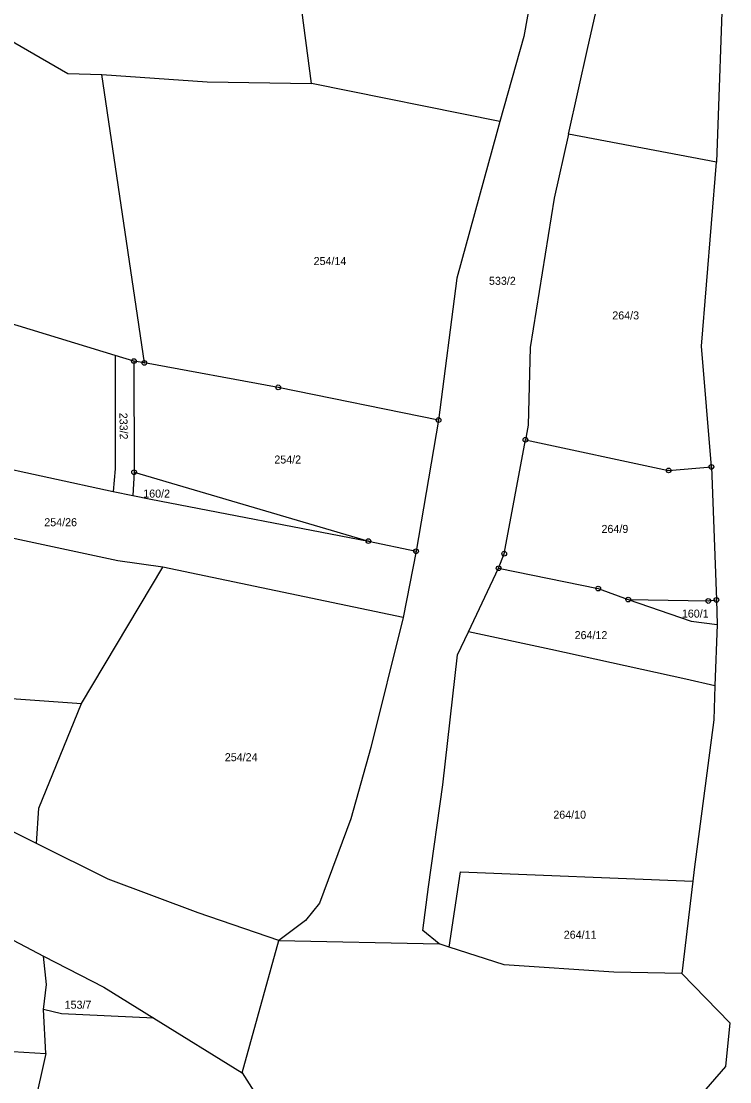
# Model space of a CAD drawing. Extents: x -725728 to -720881, y -1068679 to -1063504.
# Drawn here: x -725062.3 to -724911.7, y -1067027.7 to -1066802.4 of the extents above; entities that cross this region are included whole.
import ezdxf

# ---------------------------------------------------------------- set-up
doc = ezdxf.new("R2010")
doc.units = 0
for name, color, linetype in [('Hranice parcel', 7, 'Continuous'), ('Parcelní čísla', 7, 'Continuous'), ('Značky bodu BP', 7, 'Continuous')]:
    doc.layers.add(name, color=color, linetype=linetype)

# ---------------------------------------------------------------- blocks, each defined once
blk = doc.blocks.new('1.05_1')
at = {"layer": 'Značky bodu BP'}
for radius in [0.05, 0.00303]:
    blk.add_circle((0, 0), radius, dxfattribs=at)
blk = doc.blocks.new('1.05_2')
at = {"layer": 'Značky bodu BP'}
for radius in [0.05, 0.00303]:
    blk.add_circle((0, 0), radius, dxfattribs=at)

msp = doc.modelspace()

# ---------------------------------------------------------------- linework, layer by layer
at = {"layer": 'Hranice parcel'}
for p, q in [((-725000.59, -1066815.68), (-725010.55, -1066741.09)), ((-725036.09, -1066875.04), (-725045.16, -1066813.74)), ((-724960.58, -1066823.72), (-725000.59, -1066815.68)), ((-724914.54, -1066832.38), (-724945.99, -1066826.46)), ((-725038.32, -1066874.63), (-725042.27, -1066873.43)), ((-725038.32, -1066874.63), (-725038.29, -1066898.25)), ((-725036.09, -1066875.04), (-725038.32, -1066874.63)), ((-724973.6, -1066887.19), (-724978.39, -1066915.04)), ((-724959.66, -1066915.55), (-724955.14, -1066891.36)), ((-724915.65, -1066897.11), (-724914.58, -1066925.38)), ((-725038.29, -1066898.25), (-725038.58, -1066903.16)), ((-725038.29, -1066898.25), (-724988.52, -1066912.87)), ((-725042.75, -1066902.35), (-725038.58, -1066903.16)), ((-724988.52, -1066912.87), (-724978.39, -1066915.04)), ((-724978.39, -1066915.04), (-724981.09, -1066929.13)), ((-724960.85, -1066918.65), (-724959.66, -1066915.55)), ((-725049.48, -1066947.41), (-725032.2, -1066918.45)), ((-724981.09, -1066929.13), (-725032.2, -1066918.45)), ((-724967.25, -1066932.12), (-724960.85, -1066918.65)), ((-724960.85, -1066918.65), (-724939.69, -1066922.96)), ((-724939.69, -1066922.96), (-724933.32, -1066925.29)), ((-724914.58, -1066925.38), (-724914.39, -1066930.62)), ((-724914.39, -1066930.62), (-724914.89, -1066943.64)), ((-725117.44, -1066942.46), (-725049.48, -1066947.41)), ((-724919.62, -1066985.13), (-724921.91, -1067004.75)), ((-725015.32, -1067025.8), (-725007.51, -1066997.75)), ((-725007.51, -1066997.75), (-724973.45, -1066998.45)), ((-724971.34, -1066999.13), (-724973.45, -1066998.45)), ((-725057, -1067021.75), (-725057.49, -1067012.35)), ((-725034.06, -1067014.24), (-725015.32, -1067025.8)), ((-725057, -1067021.75), (-725074.77, -1067099.53))]:
    msp.add_line(p, q, dxfattribs=at)
for points in [[(-724943.71, -1066712.36), (-724942.26, -1066725.91), (-724945.82, -1066756.96), (-724951.11, -1066781.29), (-724955.47, -1066805.69), (-724960.58, -1066823.72)], [(-724945.99, -1066826.46), (-724941.87, -1066808.05), (-724933.67, -1066771.83), (-724930.31, -1066746.2), (-724928.58, -1066730.81)], [(-724912.15, -1066776.37), (-724913.1, -1066790.55), (-724914.54, -1066832.38)], [(-725100.64, -1066785.59), (-725052.38, -1066813.57), (-725045.16, -1066813.74)], [(-725045.16, -1066813.74), (-725022.74, -1066815.34), (-725000.59, -1066815.68)], [(-724960.58, -1066823.72), (-724961.26, -1066826.11), (-724969.71, -1066857.04), (-724973.6, -1066887.19)], [(-724945.99, -1066826.46), (-724949.03, -1066840.06), (-724954.11, -1066871.75), (-724954.56, -1066888.28), (-724955.14, -1066891.36)], [(-724915.65, -1066897.11), (-724917.76, -1066871.46), (-724914.54, -1066832.38)], [(-725042.27, -1066873.43), (-725099.08, -1066856.11), (-725117.05, -1066852.4)], [(-725042.27, -1066873.43), (-725042.27, -1066897.54), (-725042.75, -1066902.35)], [(-724973.6, -1066887.19), (-725007.66, -1066880.22), (-725036.09, -1066875.04)], [(-725125.27, -1066884.94), (-725097.48, -1066890.47), (-725042.75, -1066902.35)], [(-724955.14, -1066891.36), (-724924.73, -1066897.86), (-724915.65, -1066897.11)], [(-725032.2, -1066918.45), (-725041.72, -1066917.05), (-725097.95, -1066905.02), (-725128.28, -1066896.83)], [(-725038.58, -1066903.16), (-725034.75, -1066903.97), (-724988.52, -1066912.87)], [(-724933.32, -1066925.29), (-724919.92, -1066929.86), (-724914.39, -1066930.62)], [(-724933.32, -1066925.29), (-724916.31, -1066925.6), (-724914.58, -1066925.38)], [(-724981.09, -1066929.13), (-724988.01, -1066956.7), (-724992.27, -1066971.85), (-724998.92, -1066989.81), (-725001.9, -1066993.49), (-725007.51, -1066997.75)], [(-724973.45, -1066998.45), (-724976.91, -1066995.62), (-724975.76, -1066986.35), (-724972.67, -1066964.63), (-724969.6, -1066937.06), (-724967.25, -1066932.12)], [(-724914.89, -1066943.64), (-724921.1, -1066942.22), (-724949.74, -1066935.91), (-724967.25, -1066932.12)], [(-725152.97, -1066939.34), (-725150.85, -1066940.68), (-725130.76, -1066955.05), (-725109.55, -1066968.11), (-725086.53, -1066984.28), (-725066.53, -1066996.33), (-725057.5, -1067001.02)], [(-725059.03, -1066977.1), (-725065.09, -1066974.08), (-725088.1, -1066961.54), (-725101.87, -1066953.26), (-725115.98, -1066943.46), (-725117.44, -1066942.46)], [(-724914.89, -1066943.64), (-724915.16, -1066950.84), (-724919.33, -1066982.67), (-724919.62, -1066985.13)], [(-725059.03, -1066977.1), (-725058.54, -1066969.6), (-725049.48, -1066947.41)], [(-725007.51, -1066997.75), (-725024.69, -1066991.82), (-725043.82, -1066984.67), (-725059.03, -1066977.1)], [(-724971.34, -1066999.13), (-724968.93, -1066983.1), (-724919.62, -1066985.13)], [(-725057.49, -1067012.35), (-725056.87, -1067007.06), (-725057.5, -1067001.02)], [(-725057.5, -1067001.02), (-725044.74, -1067007.66), (-725034.06, -1067014.24)], [(-724921.91, -1067004.75), (-724936.35, -1067004.46), (-724959.68, -1067002.9), (-724971.34, -1066999.13)], [(-724921.91, -1067004.75), (-724911.74, -1067015.18), (-724912.67, -1067024.51), (-724919.19, -1067032)], [(-725034.06, -1067014.24), (-725053.68, -1067013.33), (-725057.49, -1067012.35)], [(-725098.49, -1067013.26), (-725078.1, -1067020.42), (-725057, -1067021.75)], [(-725015.32, -1067025.8), (-725010.69, -1067033.04), (-725009.25, -1067046.11), (-725013.4, -1067066.45), (-725017.8, -1067098.42), (-725020.38, -1067115.45)]]:
    msp.add_lwpolyline(points, dxfattribs=at)

# ---------------------------------------------------------------- block references
at = {"layer": 'Značky bodu BP', "xscale": 10, "yscale": 10}
for name, p in [('1.05_2', (-725038.32, -1066874.63)), ('1.05_1', (-725036.09, -1066875.04)), ('1.05_1', (-725007.66, -1066880.22)), ('1.05_1', (-724973.6, -1066887.19)), ('1.05_1', (-724955.14, -1066891.36)), ('1.05_1', (-724924.73, -1066897.86)), ('1.05_1', (-724915.65, -1066897.11)), ('1.05_1', (-725038.29, -1066898.25)), ('1.05_1', (-724988.52, -1066912.87)), ('1.05_1', (-724978.39, -1066915.04)), ('1.05_1', (-724959.66, -1066915.55)), ('1.05_2', (-724960.85, -1066918.65)), ('1.05_1', (-724939.69, -1066922.96)), ('1.05_1', (-724933.32, -1066925.29)), ('1.05_1', (-724916.31, -1066925.6)), ('1.05_2', (-724914.58, -1066925.38))]:
    msp.add_blockref(name, p, dxfattribs=at)

# ---------------------------------------------------------------- texts
at = {"layer": 'Parcelní čísla'}
for s, p in [('254/14', (-725000.15, -1066854.24)), ('533/2', (-724962.89, -1066858.44)), ('264/3', (-724936.7, -1066865.79)), ('254/2', (-725008.49, -1066896.4)), ('160/2', (-725036.34, -1066903.64)), ('254/26', (-725057.36, -1066909.72)), ('264/9', (-724938.99, -1066911.14)), ('160/1', (-724921.92, -1066929.13)), ('264/12', (-724944.7, -1066933.7)), ('254/24', (-725019.01, -1066959.63)), ('264/10', (-724949.23, -1066971.84)), ('264/11', (-724947.01, -1066997.34)), ('153/7', (-725053.04, -1067012.21))]:
    msp.add_text(s, height=1.7, dxfattribs=at).set_placement(p)
msp.add_text('233/2', height=1.7, rotation=271, dxfattribs=at).set_placement((-725041.4, -1066885.63))

doc.saveas('drawing.dxf')
